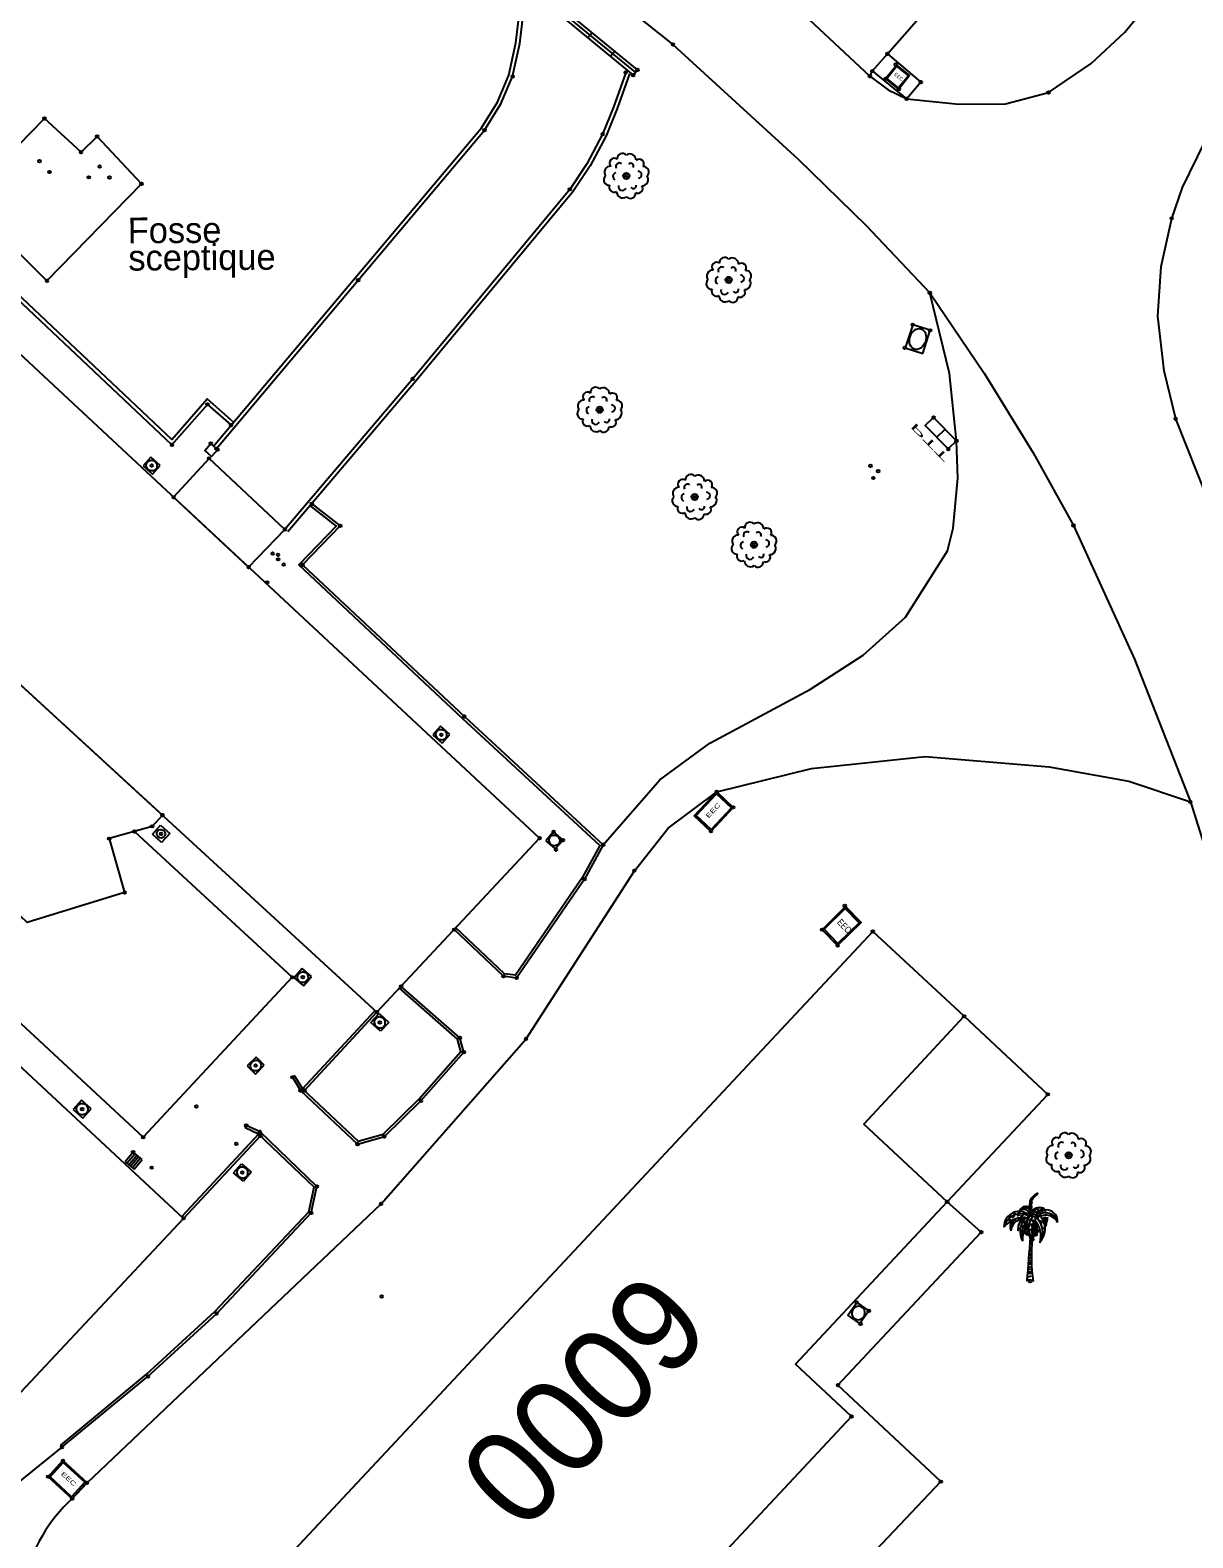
# Model space of a CAD drawing. Extents: x 344013 to 344423, y 298505 to 298795.
# Drawn here: x 344222.4 to 344267.6, y 298636.9 to 298695.5 of the extents above; entities that cross this region are included whole.
import ezdxf

# ---------------------------------------------------------------- set-up
doc = ezdxf.new("R2010")
doc.units = 0
for name, color, linetype in [('Default', 7, 'Continuous'), ('DH_CADRE -CARTOUCHE', 7, 'Continuous'), ('DH_CADRE-CARTOUCHE-NORD', 7, 'Continuous'), ('PC_CONCRETE', 7, 'Continuous'), ('PS_BOLT', 7, 'Continuous'), ('PS_CONST', 7, 'Continuous'), ('PS_DIM', 7, 'Continuous'), ('PS_HIDDEN', 7, 'Continuous'), ('RES_ELECTRICITE', 7, 'Continuous'), ('TOPO_POINT', 7, 'Continuous'), ('VOIRIE_BORDURE', 7, 'Continuous'), ('VOIRIE_ESPACE VERT', 7, 'Continuous')]:
    doc.layers.add(name, color=color, linetype=linetype)

# ---------------------------------------------------------------- blocks, each defined once
blk = doc.blocks.new('CT2')
at = {"layer": 'Default'}
blk.add_lwpolyline([(0, 0), (1, 0), (1, 1), (0, 1)], close=True, dxfattribs=at)
blk.add_lwpolyline([(0.5, 1), (0.5, 0)], dxfattribs=at)
blk.add_text('PTT', height=0.6, dxfattribs=at).set_placement((-0.3, 1.425))
blk = doc.blocks.new('REG_INC')
at = {"layer": 'Default'}
for p, q in [((0, 1), (1, 1)), ((0, 0), (0, 1)), ((1, 1), (1, 0)), ((1, 0), (0, 0))]:
    blk.add_line(p, q, dxfattribs=at)
for centre, start, end in [((0.498, 0.5), 135.00554, 180.00554), ((0.5, 0.498), 90.00577, 135.00577), ((0.5, 0.5), 45.00687, 90.00687), ((0.499, 0.499), 0.00663, 45.00663), ((0.501, 0.5), 180.00663, 225.00663), ((0.499, 0.498), 225.00686, 270.00686), ((0.499, 0.5), 270.00577, 315.00577), ((0.501, 0.499), 315.00554, 0.00554)]:
    blk.add_arc(centre, 0.44, start, end, dxfattribs=at)
blk = doc.blocks.new('R9')
at = {"layer": 'Default'}
for p, q in [((0, 0), (0, 1)), ((0, 1), (1, 1)), ((1, 0), (0, 0)), ((1, 1), (1, 0))]:
    blk.add_line(p, q, dxfattribs=at)
blk.add_circle((0.5, 0.5), 0.35, dxfattribs=at)
blk = doc.blocks.new('R5')
at = {"layer": 'Default'}
for p, q in [((0, 1), (0, 0)), ((1, 1), (0, 1)), ((0.2, 1), (0.2, 0)), ((0.4, 1), (0.4, 0)), ((0.6, 1), (0.6, 0)), ((0.8, 1), (0.8, 0)), ((1, 0), (1, 1)), ((0, 0), (1, 0)), ((0.6, 0), (0.6, 0))]:
    blk.add_line(p, q, dxfattribs=at)
blk = doc.blocks.new('RES_ELECTRICITE')
at = {"layer": 'RES_ELECTRICITE'}
for points in [[(0, 0), (0, 1), (1, 1), (1, 0)], [(0.05, 0.05), (0.05, 0.95), (0.95, 0.95), (0.95, 0.05)]]:
    blk.add_lwpolyline(points, close=True, dxfattribs=at)
blk.add_text('EEC', height=0.2, dxfattribs=at).set_placement((0.237, 0.46))
blk = doc.blocks.new('POINT_DISPLAY')
at = {"layer": 'Default'}
blk.add_circle((0, 0), 0.05, dxfattribs=at)
blk = doc.blocks.new('COCO')
at = {"layer": 'Default'}
for p, q in [((-0.026, 1.226), (0.061, 1.212)), ((0.047, 0.655), (-0.058, 0.642)), ((-0.046, 0.891), (0.052, 0.927)), ((0.054, 0.998), (-0.041, 0.985)), ((-0.037, 1.06), (0.056, 1.071)), ((0.058, 1.14), (-0.03, 1.162)), ((0.046, 0.033), (-0.076, 0.051)), ((-0.073, 0.17), (0.045, 0.209)), ((0.045, 0.292), (-0.07, 0.288)), ((-0.068, 0.371), (0.045, 0.374)), ((0.045, 0.47), (-0.065, 0.453)), ((-0.062, 0.537), (0.046, 0.552))]:
    blk.add_line(p, q, dxfattribs=at)
for points in [[(0.029, 2.551), (-0.016, 2.896), (0.002, 3.125), (0.059, 3.241), (0.173, 3.348), (0.189, 3.356), (0.282, 3.415), (0.266, 3.373), (0.2, 3.318), (0.143, 3.247), (0.093, 3.2), (0.081, 3.165), (0.057, 3.133), (0.057, 3.099), (0.06, 3.037), (0.039, 2.989), (0.039, 2.944), (0.049, 2.877), (0.037, 2.841), (0.013, 2.736)], [(-0.746, 2.559), (-0.864, 2.483)], [(-0.77, 2.413), (-0.836, 2.333)], [(-0.607, 2.534), (-0.704, 2.443)], [(-0.636, 2.639), (-0.541, 2.608)], [(-0.421, 2.58), (-0.503, 2.523)], [(-0.487, 2.68), (-0.386, 2.65)], [(-0.183, 2.493), (-0.348, 2.417), (-0.401, 2.307), (-0.448, 2.203), (-0.471, 2.086), (-0.474, 2.023), (-0.466, 1.973), (-0.455, 2.054), (-0.451, 2.146), (-0.387, 2.292), (-0.351, 2.354), (-0.284, 2.404), (-0.233, 2.445), (-0.012, 2.495)], [(-0.256, 2.553), (-0.385, 2.508)], [(0.015, 2.414), (-0.056, 2.352)], [(0.013, 2.736), (0.036, 2.813), (0.046, 2.746)], [(0.081, 2.404), (0.106, 2.299)], [(0.133, 2.608), (0.185, 2.634)], [(0.196, 2.687), (0.323, 2.715)], [(0.283, 2.765), (0.331, 2.786)], [(0.385, 2.37), (0.469, 2.254)], [(-0.321, 1.997), (-0.364, 1.9)], [(-0.276, 2.151), (-0.329, 2.086)], [(-0.203, 2.314), (-0.274, 2.258)], [(-0.23, 2.152), (-0.237, 2.043)], [(-0.161, 2.218), (-0.158, 2.122)], [(-0.059, 2.024), (-0.083, 1.998)], [(-0.04, 2.247), (-0.081, 2.179)], [(-0.025, 2.032), (0.002, 1.954)], [(0.022, 2.24), (0.043, 2.13)], [(0.473, 2.115), (0.509, 2.012)], [(-0.055, 0.716), (0.048, 0.717), (0.049, 0.787), (-0.051, 0.795)]]:
    blk.add_lwpolyline(points, dxfattribs=at)
for centre, radius in [((-0.187, 1.897), 0.0384), ((-0.144, 1.978), 0.0616), ((-0.124, 1.896), 0.0376), ((-0.11, 1.84), 0.0471), ((0.134, 1.862), 0.0549), ((0.208, 1.822), 0.0626), ((0.254, 1.938), 0.0628)]:
    blk.add_circle(centre, radius, dxfattribs=at)
for centre, radius, start, end in [((-0.427, 2.113), 0.595, 43.61211, 181.46245), ((-0.291, 1.543), 0.918, 76.73894, 142.80251), ((-0.38, 1.964), 0.648, 57.91917, 166.62012), ((-0.3, 2.12), 0.482, 151.13313, 199.59422), ((-0.196, 1.874), 0.565, 78.51401, 171.35044), ((-0.32, 2.055), 0.433, 119.08336, 188.76207), ((-0.123, 2.59), 0.323, 122.34745, 158.76357), ((-0.199, 2.618), 0.238, 4.52184, 154.10099), ((-0.252, 2.556), 0.231, 4.24411, 134.21032), ((0.362, 1.922), 0.754, 136.71129, 208.82208), ((0.551, 1.79), 0.879, 137.73301, 194.37159), ((-0.16, 2.647), 0.255, 21.08609, 122.34745), ((0.62, 2.159), 0.753, 153.08677, 230.11243), ((0.659, 2.068), 0.718, 142.35537, 222.27942), ((-0.007, 2.465), 0.0563, 81.74752, 144.30354), ((-0.189, 1.21), 1.324, 71.37146, 81.74752), ((0.376, 2.508), 0.372, 113.76809, 175.33093), ((0.376, 2.508), 0.372, 113.76809, 175.33093), ((0.294, 2.595), 0.256, 198.67654, 199.76266), ((0.963, 1.939), 0.9, 143.98655, 203.42885), ((0.418, 2.527), 0.326, 97.12484, 183.95116), ((1.025, 2.053), 0.958, 126.68582, 153.16638), ((0.59, 2.015), 0.548, 29.56544, 139.35171), ((-0.543, 1.744), 0.96, 344.8781, 41.14605), ((-0.341, 1.9), 0.828, 46.97669, 50.12313), ((0.618, 2.316), 0.451, 356.16265, 159.00089), ((0.609, 2.187), 0.468, 12.10772, 148.31459), ((0.344, 2.407), 0.451, 69.08173, 104.86204), ((-0.157, 2.027), 0.74, 51.24751, 54.5217), ((-0.341, 1.9), 0.828, 334.06866, 41.194), ((-1.005, 1.577), 1.786, 37.56679, 40.51564), ((-0.157, 2.027), 0.74, 315.14717, 39.02392), ((-0.254, 2.28), 0.869, 28.47252, 37.09653), ((0.493, 2.767), 0.0679, 35.32051, 126.68582), ((-1.704, 1.849), 2.327, 7.59784, 16.36658), ((-0.054, 2.379), 0.738, 25.81944, 35.32051), ((-0.254, 2.28), 0.869, 350.88829, 14.70633), ((-0.482, 2.552), 1.161, 339.35966, 356.59253), ((0.649, 1.599), 0.949, 145.51456, 182.45279), ((-0.279, 1.637), 0.281, 2.14987, 36.63246), ((0.544, 1.816), 0.474, 137.19533, 172.89867), ((0.308, 2.014), 0.226, 121.42967, 182.28997), ((27.302, 0.106), 27.266, 175.47911, 176.55971), ((0.311, 2.152), 0.219, 141.85595, 191.51747), ((0.372, 1.847), 0.277, 133.59561, 173.48701), ((0.808, 1.542), 0.777, 142.23578, 156.28002), ((0.242, 1.964), 0.147, 110.97274, 165.97557), ((0.404, 1.878), 0.354, 125.05854, 146.38926), ((0.398, 2.098), 0.301, 136.45687, 162.06855), ((0.357, 2.084), 0.244, 133.11836, 172.75341), ((-0.759, 1.958), 0.922, 344.85055, 15.89877), ((-0.404, 2.045), 0.619, 329.46655, 26.67931), ((-0.289, 2.11), 0.564, 317.8279, 12.33856), ((-85.428, 7.294), 85.622, 355.11326, 356.26352), ((-0.265, 1.505), 0.316, 339.99973, 25.72283), ((0.199, 1.66), 0.176, 166.9443, 185.59662)]:
    blk.add_arc(centre, radius, start, end, dxfattribs=at)
blk.add_ellipse((27.425, 0.272), major_axis=(-27.371, 0.966), ratio=0.529859, start_param=6.255729, end_param=6.369141, dxfattribs=at)
blk = doc.blocks.new('ARB1')
at = {"layer": 'Default'}
blk.add_circle((0, 0), 0.122, dxfattribs=at)
for centre, radius, start, end in [((-0.471, 0.503), 0.183, 53.95544, 222.20655), ((-0.153, 0.664), 0.211, 43.69255, 183.5969), ((0.139, 0.613), 0.241, 358.45835, 125.19284), ((0.501, 0.468), 0.183, 325.14445, 131.01755), ((-0.613, 0.139), 0.241, 88.45835, 215.19284), ((-0.373, -0.024), 0.149, 103.70924, 242.34652), ((-0.276, 0.37), 0.134, 52.43963, 209.54959), ((0.164, 0.38), 0.112, 330.58954, 133.71274), ((0.458, 0.052), 0.137, 276.62143, 88.96702), ((0.613, -0.139), 0.241, 268.45835, 35.19284), ((0.664, 0.153), 0.211, 313.69255, 93.5969), ((-0.664, -0.153), 0.211, 133.69255, 273.5969), ((-0.478, -0.443), 0.19, 155.22426, 300.93774), ((-0.163, -0.42), 0.148, 159.53711, 338.16632), ((0.271, -0.38), 0.112, 210.58954, 13.71274), ((0.448, -0.483), 0.188, 243.13234, 33.02965), ((-0.139, -0.613), 0.241, 178.45835, 305.19284), ((0.153, -0.664), 0.211, 223.69255, 3.5969)]:
    blk.add_arc(centre, radius, start, end, dxfattribs=at)

msp = doc.modelspace()

# ---------------------------------------------------------------- linework, layer by layer
at = {"layer": 'DH_CADRE -CARTOUCHE'}
msp.add_lwpolyline([(344227.517, 298664.97), (344227.114, 298664.539), (344225.446, 298664.062), (344226.044, 298661.968), (344222.259, 298660.802), (344220.242, 298662.699), (344218.145, 298660.448), (344195.697, 298681.448), (344202.162, 298688.436), (344213.563, 298677.785), (344227.517, 298664.97)], dxfattribs=at)
for points in [[(344213.563, 298677.785), (344235.857, 298657.311), (344242.178, 298664.083), (344220.032, 298684.709)], [(344206.167, 298669.932), (344199.92, 298663.204), (344222.021, 298642.559), (344228.339, 298649.299)], [(344230.773, 298634.4), (344238.733, 298626.952), (344246.838, 298635.519), (344247.786, 298634.617), (344254.303, 298641.591), (344252.122, 298643.632), (344258.027, 298649.94), (344254.781, 298652.961), (344258.683, 298657.153), (344255.137, 298660.451)]]:
    msp.add_lwpolyline(points, close=True, dxfattribs=at)
at = {"layer": 'PC_CONCRETE'}
msp.add_lwpolyline([(344241.5, 298697.468), (344245.902, 298693.849)], dxfattribs=at)
at = {"layer": 'PS_BOLT'}
for points in [[(344257.53, 298703.46), (344253.822, 298699.555), (344249.529, 298698.855), (344255.02, 298693.71), (344255.118, 298693.908), (344255.706, 298694.579), (344261.085, 298700.705)], [(344261.963, 298693.07), (344261.963, 298693.07)], [(344245.974, 298623.847), (344245.03, 298624.565), (344244.572, 298625.398), (344243.566, 298628.301), (344245.252, 298627.821), (344246.504, 298628.1), (344247.021, 298628.689), (344248.634, 298628.526), (344249.747, 298627.457), (344252.49, 298624.988), (344257.209, 298630.281), (344253.004, 298634.029), (344257.777, 298639.062), (344253.777, 298642.812), (344259.352, 298648.759), (344258.027, 298649.94)]]:
    msp.add_lwpolyline(points, dxfattribs=at)
for points in [[(344255.706, 298694.579), (344256.998, 298693.469), (344256.452, 298692.824), (344255.118, 298693.908)], [(344222.928, 298692.059), (344219.848, 298688.907), (344223.024, 298685.745), (344226.701, 298689.518), (344224.975, 298691.361), (344224.35, 298690.749)], [(344230.865, 298674.619), (344232.277, 298676.082), (344229.329, 298678.847), (344227.951, 298677.333)]]:
    msp.add_lwpolyline(points, close=True, dxfattribs=at)
at = {"layer": 'PS_DIM'}
msp.add_lwpolyline([(344254.781, 298652.961), (344258.683, 298657.153), (344261.94, 298654.12), (344258.027, 298649.94)], close=True, dxfattribs=at)
msp.add_lwpolyline([(344258.683, 298657.153), (344261.94, 298654.12), (344258.027, 298649.94)], dxfattribs=at)
at = {"layer": 'PS_HIDDEN'}
msp.add_lwpolyline([(344226.423, 298664.341), (344232.564, 298658.67), (344226.766, 298652.449), (344218.145, 298660.448)], dxfattribs=at)
at = {"layer": 'VOIRIE_BORDURE'}
for points in [[(344241.864, 298699.32), (344247.363, 298694.936), (344252.226, 298690.481), (344254.877, 298687.903), (344257.352, 298685.28), (344259.461, 298682.157), (344261.367, 298679.065), (344262.938, 298676.235), (344265.307, 298671.038), (344267.481, 298665.493), (344268.766, 298661.408)], [(344229.502, 298679.321), (344235.009, 298685.869), (344239.915, 298691.695), (344240.541, 298692.702), (344240.986, 298693.742), (344241.26, 298695.003), (344241.373, 298695.963), (344241.302, 298696.882), (344241.164, 298697.869)], [(344229.617, 298679.224), (344235.124, 298685.773), (344240.037, 298691.607), (344240.674, 298692.632), (344241.129, 298693.696), (344241.409, 298694.979), (344241.524, 298695.96), (344241.451, 298696.898), (344241.312, 298697.89)], [(344255.02, 298693.71), (344255.732, 298693.172), (344256.452, 298692.824), (344258.472, 298692.615), (344260.292, 298692.633), (344261.963, 298693.07), (344263.617, 298694.205), (344264.925, 298695.421), (344265.995, 298696.731)], [(344245.527, 298693.846), (344245.054, 298692.507), (344244.628, 298691.45), (344244.011, 298690.297), (344243.352, 298689.305), (344237.244, 298681.936), (344232.277, 298676.082)], [(344245.668, 298693.796), (344245.194, 298692.454), (344244.764, 298691.386), (344244.14, 298690.22), (344243.472, 298689.216), (344237.359, 298681.84), (344232.391, 298675.985)], [(344271.939, 298667.741), (344266.911, 298680.387), (344266.458, 298682.248), (344266.213, 298684.376), (344266.341, 298686.309), (344266.753, 298688.178), (344267.172, 298689.375), (344268.043, 298691.158)], [(344218.426, 298686.806), (344219.242, 298687.726), (344227.876, 298679.586), (344229.255, 298681.159), (344230.281, 298680.25)], [(344218.501, 298686.664), (344219.252, 298687.511), (344227.886, 298679.371), (344229.269, 298680.947), (344230.182, 298680.138)], [(344244.649, 298663.817), (344246.851, 298666.344), (344248.803, 298667.768), (344252.707, 298669.877), (344254.764, 298671.195), (344256.399, 298672.672), (344258.035, 298675.256), (344258.251, 298676.139), (344258.442, 298678.083), (344258.386, 298679.528), (344258.113, 298682.149), (344257.352, 298685.28)], [(344233.257, 298677.005), (344234.276, 298676.215), (344232.818, 298674.703), (344239.187, 298668.736), (344244.524, 298663.796), (344243.838, 298662.536), (344241.238, 298658.749), (344240.82, 298658.803), (344238.925, 298660.597)], [(344233.322, 298677.082), (344234.425, 298676.226), (344232.96, 298674.707), (344239.255, 298668.809), (344244.649, 298663.817), (344243.923, 298662.483), (344241.286, 298658.642), (344240.775, 298658.709), (344238.857, 298660.524)], [(344224.003, 298638.398), (344224.585, 298639.016), (344236.014, 298649.859), (344241.653, 298656.275), (344245.864, 298662.815), (344247.172, 298664.468), (344249.064, 298665.88), (344252.756, 298666.794), (344257.174, 298667.254), (344261.991, 298666.86), (344265.088, 298666.293), (344267.481, 298665.493)], [(344232.567, 298654.782), (344232.885, 298654.271), (344235.099, 298652.184), (344236.145, 298652.483), (344237.565, 298653.87), (344239.231, 298655.762), (344239.079, 298656.316), (344236.796, 298658.317)], [(344232.567, 298654.782), (344232.652, 298654.835), (344232.963, 298654.335), (344235.126, 298652.296), (344236.094, 298652.572), (344237.492, 298653.939), (344239.12, 298655.788), (344238.991, 298656.261), (344236.73, 298658.242)], [(344232.963, 298654.335), (344235.784, 298657.379)], [(344233.036, 298654.266), (344235.857, 298657.311)], [(344223.547, 298640.473), (344226.888, 298643.225), (344229.555, 298645.674), (344233.208, 298649.557), (344233.415, 298650.508), (344231.252, 298652.575), (344230.728, 298652.82)], [(344223.61, 298640.396), (344226.953, 298643.149), (344229.625, 298645.603), (344233.3, 298649.509), (344233.524, 298650.541), (344231.309, 298652.658), (344230.771, 298652.911)], [(344230.771, 298652.911), (344230.728, 298652.82)], [(344231.253, 298652.574), (344228.265, 298649.367)], [(344231.325, 298652.505), (344228.339, 298649.299)], [(344223.61, 298640.396), (344220.335, 298637.772)], [(344223.547, 298640.473), (344223.61, 298640.396)]]:
    msp.add_lwpolyline(points, dxfattribs=at)
msp.add_lwpolyline([(344229.661, 298679.185), (344229.427, 298678.925), (344229.167, 298679.159), (344229.401, 298679.419)], close=True, dxfattribs=at)
msp.add_arc((344228.199, 298633.832), 6.201, 132.57867, 200.9263, dxfattribs=at)

# ---------------------------------------------------------------- block references
at = {"layer": 'DH_CADRE-CARTOUCHE-NORD', "xscale": 1.271052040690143, "yscale": -0.45334297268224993, "rotation": -45.69966}
msp.add_blockref('CT2', (344257.498, 298680.438), dxfattribs=at)
at = {"layer": 'PC_CONCRETE'}
for name, p, xscale, yscale, rotation in [('R5', (344241.417, 298697.367), 5.698532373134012, 0.26107124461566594, -39.41910000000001), ('REG_INC', (344256.684, 298684.042), 0.7121922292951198, -0.9465818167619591, -17.711370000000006), ('REG_INC', (344227.064, 298678.898), 0.4871224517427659, -0.45832881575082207, -41.48739000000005), ('REG_INC', (344238.326, 298668.436), 0.4871224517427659, -0.45832881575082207, -41.48739000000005), ('R9', (344227.797, 298664.265), 0.4854069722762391, 0.46797190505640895, 138.23675999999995), ('REG_INC', (344242.724, 298664.325), 0.4871224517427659, -0.45832881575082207, -41.48739000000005), ('REG_INC', (344232.95, 298659.01), 0.471537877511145, -0.47955543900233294, -40.69179000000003), ('REG_INC', (344235.621, 298656.911), 0.50075578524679, 0.47476162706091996, -42.81560999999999), ('REG_INC', (344231.154, 298655.571), 0.453964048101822, -0.490300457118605, -44.96589), ('REG_INC', (344224.044, 298653.53), 0.49360458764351, -0.5065070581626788, 48.236309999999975), ('R5', (344226.723, 298651.581), 0.45155761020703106, 0.48498859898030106, 140.06735999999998), ('REG_INC', (344230.281, 298651.065), 0.505532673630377, 0.46824879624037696, -40.18680000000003), ('REG_INC', (344254.978, 298645.702), 0.5714075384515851, 0.600851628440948, 145.21355999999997)]:
    msp.add_blockref(name, p, dxfattribs=dict(at, xscale=xscale, yscale=yscale, rotation=rotation))
at = {"layer": 'RES_ELECTRICITE'}
for p, xscale, yscale, rotation in [((344255.631, 298693.61), 0.655245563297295, 0.6769608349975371, -38.725379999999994), ((344248.839, 298664.345), 1.2754888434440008, 0.8829583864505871, 46.97414999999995), ((344253.16, 298660.522), 0.8641838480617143, 1.2814348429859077, -45.62847000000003), ((344223.069, 298639.255), 1.267131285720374, 0.8493452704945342, -42.500046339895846)]:
    msp.add_blockref('RES_ELECTRICITE', p, dxfattribs=dict(at, xscale=xscale, yscale=yscale, rotation=rotation))
at = {"layer": 'TOPO_POINT'}
for p in [(344247.363, 298694.936), (344255.706, 298694.579), (344256.029, 298694.16), (344241.129, 298693.696), (344245.527, 298693.846), (344245.819, 298693.748), (344245.985, 298693.95), (344255.02, 298693.71), (344255.118, 298693.908), (344255.631, 298693.61), (344256.143, 298693.2), (344256.998, 298693.469), (344261.963, 298693.07), (344256.452, 298692.824), (344222.928, 298692.059), (344224.975, 298691.361), (344240.037, 298691.607), (344244.628, 298691.45), (344224.35, 298690.749), (344222.738, 298690.404), (344225.076, 298690.191), (344223.124, 298689.981), (344224.654, 298689.773), (344225.458, 298689.767), (344226.701, 298689.518), (344245.552, 298689.828), (344243.352, 298689.305), (344266.753, 298688.178), (344223.024, 298685.745), (344235.124, 298685.773), (344249.533, 298685.786), (344257.352, 298685.28), (344256.684, 298684.042), (344257.363, 298683.825), (344256.372, 298683.148), (344237.244, 298681.936), (344229.269, 298680.947), (344244.517, 298680.736), (344230.182, 298680.138), (344257.498, 298680.438), (344266.911, 298680.387), (344258.386, 298679.528), (344227.886, 298679.371), (344229.398, 298679.422), (344229.617, 298679.224), (344229.661, 298679.185), (344258.073, 298679.2), (344227.095, 298678.565), (344229.329, 298678.847), (344255.041, 298678.559), (344255.341, 298678.35), (344255.156, 298678.083), (344227.951, 298677.333), (344248.21, 298677.345), (344233.322, 298677.082), (344232.277, 298676.082), (344234.425, 298676.226), (344262.938, 298676.235), (344250.515, 298675.487), (344231.801, 298675.144), (344232.005, 298675.1), (344232.015, 298674.92), (344230.865, 298674.619), (344232.228, 298674.716), (344232.96, 298674.707), (344231.59, 298674.028), (344239.255, 298668.809), (344238.356, 298668.102), (344249.064, 298665.88), (344267.481, 298665.493), (344227.517, 298664.97), (344249.71, 298665.278), (344226.423, 298664.341), (344227.114, 298664.539), (344242.724, 298664.325), (344248.839, 298664.345), (344225.446, 298664.062), (344227.461, 298664.251), (344242.178, 298664.083), (344243.088, 298664.003), (344244.649, 298663.817), (344242.817, 298663.631), (344245.864, 298662.815), (344226.044, 298661.968), (344243.923, 298662.483), (344254.044, 298661.451), (344238.857, 298660.524), (344253.16, 298660.522), (344255.137, 298660.451), (344253.765, 298659.904), (344232.564, 298658.67), (344232.973, 298658.675), (344240.775, 298658.709), (344241.286, 298658.642), (344236.796, 298658.317), (344235.857, 298657.311), (344235.966, 298656.914), (344258.683, 298657.153), (344239.079, 298656.316), (344241.653, 298656.275), (344239.231, 298655.762), (344231.142, 298655.238), (344232.567, 298654.782), (344232.885, 298654.271), (344233.036, 298654.266), (344237.565, 298653.87), (344261.94, 298654.12), (344224.396, 298653.546), (344228.835, 298653.645), (344230.771, 298652.911), (344231.309, 298652.658), (344226.766, 298652.449), (344230.388, 298652.195), (344231.325, 298652.505), (344235.099, 298652.184), (344236.145, 298652.483), (344226.377, 298651.871), (344262.745, 298651.752), (344227.098, 298651.268), (344230.625, 298651.081), (344233.524, 298650.541), (344236.014, 298649.859), (344258.027, 298649.94), (344228.339, 298649.299), (344233.3, 298649.509), (344259.352, 298648.759), (344261.251, 298646.858), (344236.039, 298646.262), (344229.625, 298645.603), (344254.509, 298646.028), (344254.978, 298645.702), (344254.654, 298645.196), (344226.953, 298643.149), (344253.777, 298642.812), (344254.303, 298641.591), (344223.61, 298640.396), (344223.653, 298639.872), (344223.069, 298639.255), (344257.777, 298639.062), (344224.585, 298639.016), (344224.003, 298638.398)]:
    msp.add_blockref('POINT_DISPLAY', p, dxfattribs=at)
at = {"layer": 'VOIRIE_ESPACE VERT'}
for name, p in [('ARB1', (344245.552, 298689.828)), ('ARB1', (344249.533, 298685.786)), ('ARB1', (344244.517, 298680.736)), ('ARB1', (344248.21, 298677.345)), ('ARB1', (344250.515, 298675.487)), ('ARB1', (344262.745, 298651.752)), ('COCO', (344261.251, 298646.858))]:
    msp.add_blockref(name, p, dxfattribs=at)

# ---------------------------------------------------------------- texts
at = {"layer": 'PS_CONST'}
for s, height, rotation, p in [('Fosse', 1.0003, 0.36649, (344226.169, 298687.208)), ('sceptique', 1.0003, 0.36649, (344226.192, 298686.146)), ('0009', 3.662, 46.56081, (344241.491, 298636.993))]:
    msp.add_text(s, height=height, rotation=rotation, dxfattribs=at).set_placement(p)

doc.saveas('drawing.dxf')
